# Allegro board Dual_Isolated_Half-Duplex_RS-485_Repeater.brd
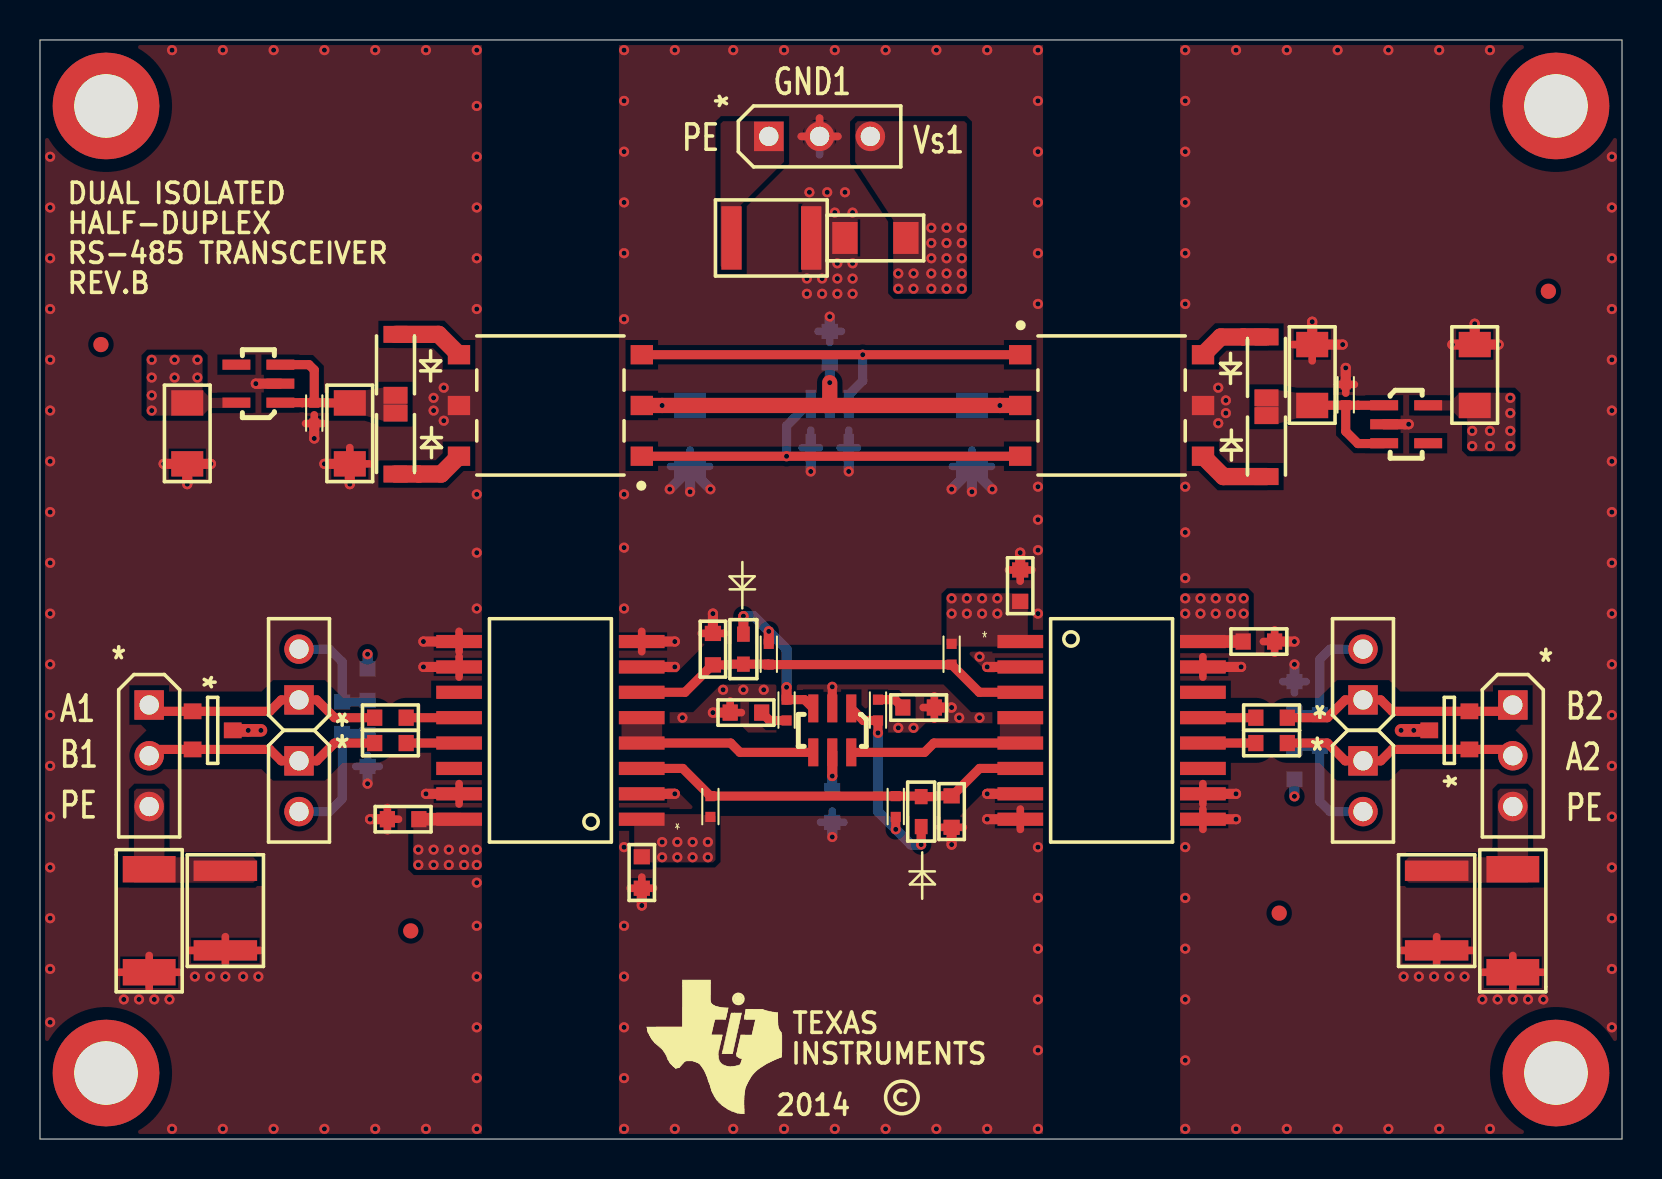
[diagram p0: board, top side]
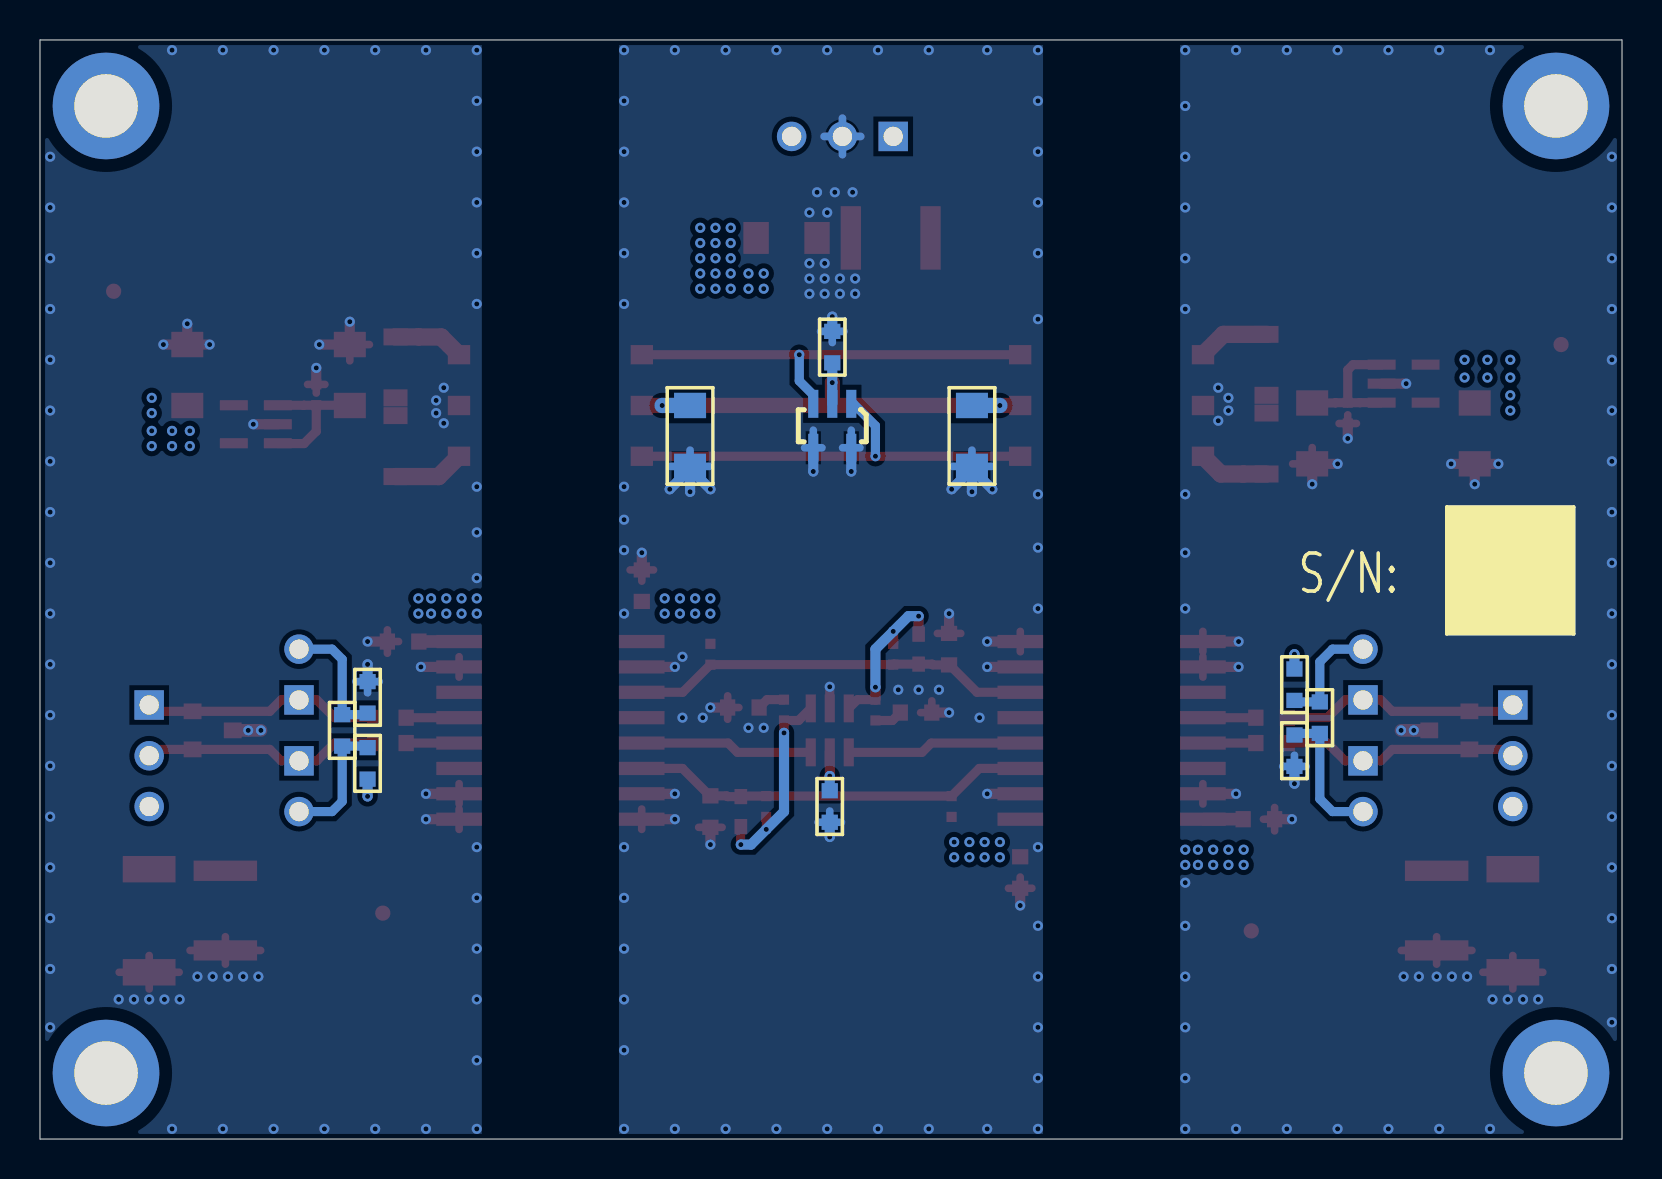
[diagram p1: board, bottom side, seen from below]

Outline 79.12 x 54.99 mm; copper layers: TOP, L2 GND, L3 PWR, BOTTOM. Coordinates in mm from the lower left corner of the outline.
Outline path: 0,54.99 79.12,54.99 79.12,0 0,0 0,54.99

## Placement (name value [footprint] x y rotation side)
C1  4.7uF  [1206]  41.78 45.09 180 top
C2  4700pF  [1812]  36.58 45.09 180 top
C3  0.1uF  [0603]  39.5 39.62 90 bottom
C4  4.7uF  [1206]  32.51 35.18 90 bottom
C5  4.7uF  [1206]  46.61 35.18 90 bottom
C6  4.7uF  [1206]  15.49 35.31 270 top
C7  10.0nF  [0402]  13.72 36.32 270 top
C8  4.7uF  [1206]  7.37 35.31 270 top
C9  4.7uF  [1206]  63.63 38.23 90 top
C10  10.0nF  [0402]  65.3 37.24 90 top
C11  4.7uF  [1206]  71.75 38.23 90 top
C12  4700pF  [1812]  9.27 11.43 90 top
C13  0.1uF  [0603]  18.16 16 0 top
C14  0.1uF  [0603]  30.1 13.34 90 top
C15  0.1uF  [0603]  39.62 16.64 270 bottom
C16  100pF  [0603]  35.31 21.34 0 top
C17  100pF  [0603]  43.94 21.59 0 top
C18  0.1uF  [0603]  49.02 27.69 270 top
C19  0.1uF  [0603]  60.96 24.89 0 top
C20  4700pF  [1812]  69.85 11.43 270 top
C21  100pF  [0603]  33.66 24.51 270 top
C22  100pF  [0603]  45.59 16.38 90 top
D1  RB168M-40  [DIODE_SOD_123F]  17.78 38.73 90 top
D2  RB168M-40  [DIODE_SOD_123F]  17.78 34.8 270 top
D3  RB168M-40  [DIODE_SOD_123F]  61.34 38.61 90 top
D4  RB168M-40  [DIODE_SOD_123F]  61.34 34.67 270 top
D5  SM712  [SOT_23_321]  8.64 20.45 270 top
D6  1N4448WT  [SOD_523]  35.18 24.51 270 top
D7  1N4448WT  [SOD_523]  44.07 16.38 90 top
D8  SM712  [SOT_23_321]  70.48 20.45 90 top
J1  HMTSW-103-07-G-S-.240  [HDR_THVT_1X3_100]  36.45 50.16 90 top
J2  1725669  [HDR_THVT_1X3_100]  5.46 21.72 0 top
J3  1725669  [HDR_THVT_1X3_100]  73.66 21.72 0 top
JP1  HEADER_1x2_100_430L  [HDR_THVT_1X2_100]  12.95 18.92 0 top
JP2  HEADER_1x2_100_430L  [HDR_THVT_1X2_100]  12.95 21.97 180 top
JP3  HEADER_1x2_100_430L  [HDR_THVT_1X2_100]  66.17 18.92 0 top
JP4  HEADER_1x2_100_430L  [HDR_THVT_1X2_100]  66.17 21.97 180 top
M*  -  [unnamed]  75.82 3.3 0 top
M*#2  -  [unnamed]  3.3 51.69 0 top
M*#3  -  [unnamed]  75.82 51.69 0 top
M*#4  -  [unnamed]  3.3 3.3 0 top
NOREF  -  [unnamed]  75.44 42.42 0 top
NOREF#2  -  [#2]  0 54.99 0 top
NOREF#3  -  [unnamed]  3.05 39.75 0 top
NOREF#4  -  [#2]  0 0 90 top
NOREF#5  -  [#2]  30.35 1.27 0 top
NOREF#6  -  [#2]  80.77 0.64 0 top
NOREF#7  -  [unnamed]  18.54 10.41 0 top
NOREF#8  -  [unnamed]  61.98 11.3 0 top
NOREF#9  -  [#2]  48.01 6.86 180 bottom
NOREF#10  -  [#2]  14.73 6.22 180 bottom
NOREF#11  -  [#2]  15.75 28.45 180 bottom
R1  590  [0603]  16.38 22.73 270 bottom
R2  133  [0603]  15.11 21.08 270 bottom
R3  590  [0603]  16.38 19.43 270 bottom
R4  10  [0603]  17.53 21.08 0 top
R5  10  [0603]  17.53 19.81 0 top
R6  1M  [2010]  5.46 10.92 90 top
R7  10K  [0402]  33.53 16.64 90 top
R8  51  [0402]  36.45 24.26 90 top
R9  51  [0402]  42.8 16.64 90 top
R10  10K  [0402]  45.59 24.26 270 top
R11  10  [0603]  61.59 19.81 0 top
R12  10  [0603]  61.59 21.08 0 top
R13  1M  [2010]  73.66 10.92 270 top
R14  590  [0603]  62.74 18.8 90 bottom
R15  133  [0603]  64.01 20.45 90 bottom
R16  590  [0603]  62.74 22.1 90 bottom
R17  300  [0402]  37.34 21.46 270 top
R18  300  [0402]  41.91 21.46 90 top
T1  WE 760390014  [TFMR_6_281X265]  25.53 36.7 180 top
T2  WE 760390014  [TFMR_6_281X265]  53.59 36.7 0 top
U1  SN6501DBV  [SOT23_5]  39.5 35.69 270 bottom
U2  TPS76350DBV  [SOT23_5]  10.92 37.8 180 top
U3  TPS76350DBV  [SOT23_5]  68.33 35.76 0 top
U4  ISO3082DW  [SOIC_16_410X299_50]  25.53 20.45 180 top
U5  ISO3082DW  [SOIC_16_410X299_50]  53.59 20.45 0 top
U6  SN74LVC2G14DBV  [SOT23_6]  39.62 20.45 270 top

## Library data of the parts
C1 C2 C4 C5 C12 C20 = CAP_1206_2.2uF
C3 C13-C15 C18 C19 = CAP_0603_0.1uF_H
C6 C8 C9 C11 = CAP_1206_10uF
C7 C10 = CAP_0402_0.001uF
C16 C17 C21 C22 = CAP_0603_100pF
D1-D4 = DIODE_MA2S78400L_1
D5 D8 = DIODE_TVS
D6 D7 = DIODE_10BQ060
J1 = HEADER_1x3_100
J2 J3 = HEADER_1x3_7
JP1-JP4 = JUMPER_1x2_100
R1-R3 R14-R16 = Res_0603_330
R4 R5 R11 R12 = Res_0603_10
R6 R13 = RES_1206_H
R7 R10 = Res_0402_10k
R8 R9 R17 R18 = Res_0402_49.9
T1 T2 = TFMR_6_WE-PP_760390014
U1 = SN6501DBV
U2 U3 = TPS76350DBV
U4 U5 = ISO3082DW
U6 = SN74LVC2G14DBV

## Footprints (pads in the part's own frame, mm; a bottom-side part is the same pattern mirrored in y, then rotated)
0402
  rect 0.508x0.508 smd: 1(-0.521,0) 2(0.521,0)
0603
  rect 0.762x0.813 smd: 1(-0.787,0) 2(0.787,0)
1206
  rect 1.27x1.6 smd: 1(-1.524,0) 2(1.524,0)
1812
  rect 1.016x3.175 smd: 1(-1.994,0) 2(1.994,0)
2010
  rect 1.321x2.642 smd: 1(-2.578,0) 2(2.578,0)
DIODE_SOD_123F
  rect 0.85x1.2 smd: 1(-1.525,0) 2(1.525,0)
HDR_THVT_1X2_100
  rect 1.473x1.473 hole 0.965: 1(0,0)
  round 1.473 hole 0.965: 2(0,-2.54)
HDR_THVT_1X3_100
  rect 1.473x1.473 hole 0.965: 1(0,0)
  round 1.473 hole 0.965: 2(0,-2.54) 3(0,-5.08)
SOD_523
  rect 0.762x0.635 smd: 1(0.75,0) 2(-0.75,0)
SOIC_16_410X299_50
  rect 2.286x0.66 smd: 1(-4.566,4.445) 2(-4.566,3.175) 3(-4.566,1.905) 4(-4.566,0.635) 5(-4.566,-0.635) 6(-4.566,-1.905) 7(-4.566,-3.175) 8(-4.566,-4.445) 9(4.566,-4.445) 10(4.566,-3.175) 11(4.566,-1.905) 12(4.566,-0.635) 13(4.566,0.635) 14(4.566,1.905) 15(4.566,3.175) 16(4.566,4.445)
SOT23_5
  rect 1.397x0.508 smd: 1(-1.1,0.95) 2(-1.1,0) 3(-1.1,-0.95) 4(1.1,-0.95) 5(1.1,0.95)
SOT23_6
  rect 1.397x0.508 smd: 1(-1.1,0.95) 2(-1.1,0) 3(-1.1,-0.95) 4(1.1,-0.95) 5(1.1,0) 6(1.1,0.95)
SOT_23_321
  rect 0.787x0.889 smd: 1(-0.953,-1.003) 2(0.953,-1.003) 3(0,1.003)
TFMR_6_281X265
  rect 1.118x0.965 smd: 1(-4.572,2.54) 2(-4.572,0) 3(-4.572,-2.54) 4(4.572,-2.54) 5(4.572,0) 6(4.572,2.54)
unnamed
  round 0.762 smd: (0,0)

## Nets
GND: C9.2 C10.2 C11.2 C19.2 C20.2 D8.3 R13.2 R16.2 T2.5(SECONDARY_CT) U3.2(GND) U5.9(GND2#9) U5.10(GND2#10) U5.15(GND2#15)
GND_SIGNAL: C6.2 C7.2 C8.2 C12.1 C13.1 D5.3 R3.2 R6.1 T1.5(SECONDARY_CT) U2.2(GND) U4.9(GND2#9) U4.10(GND2#10) U4.15(GND2#15)
0: C1.2 C2.1 C3.2 C4.1 C5.1 C14.1 C15.2 C16.1 C17.2 C18.1 C21.1 C22.1 J1.2 U1.4(GND#4) U1.5(GND#5) U4.2(GND1#2) U4.7(GND1#7) U4.8(GND1#8) U5.2(GND1#2) U5.7(GND1#7) U5.8(GND1#8) U6.2(GND)
VS1: C1.1 C3.1 C4.2 C5.2 C14.2 C15.1 C18.2 J1.3 R7.1 R10.1 T1.2(PRIMARY_CT) T2.2(PRIMARY_CT) U1.2(VCC) U4.1(VCC1) U5.1(VCC1) U6.5(VCC)
VS2: C8.1 C13.2 R1.1 U2.5(OUT) U4.16(VCC2)
VS3: C11.1 C19.1 R14.1 U3.5(OUT) U5.16(VCC2)
N6187763: C6.1 C7.1 D1.1(A) D2.1(A) U2.1(IN) U2.3(EN)
N6187778: C9.1 C10.1 D3.1(A) D4.1(A) U3.1(IN) U3.3(EN)
N6187816: T1.3(PRIMARY) T2.1(PRIMARY_DOT) U1.3(D2)
N6187836: T1.1(PRIMARY_DOT) T2.3(PRIMARY) U1.1(D1)
N6188463: D4.2(C) T2.4(SECONDARY)
N6189820: JP2.2 R1.2 R2.1
N6189824: JP1.2 R2.2 R3.1
N6189852: JP3.2 R14.2 R15.1
N6189856: JP4.2 R15.2 R16.1
N6190014: D5.1 J2.1 JP2.1 R4.1
N6190029: D5.2 J2.2 JP1.1 R5.1
N6190181: D8.2 J3.1 JP4.1 R12.2
N6190196: D8.1 J3.2 JP3.1 R11.2
N6190760: C2.2 J1.1
N6191068: C12.2 J2.3 R6.2
N6191267: C20.1 J3.3 R13.1
N6191867: D6.2(ANODE) R8.2 R17.1 U6.3(2A)
N6191878: D7.2(ANODE) R9.1 R18.1 U6.1(1A)
N6193179: R5.2 U4.13(B)
N6193213: R4.2 U4.12(A)
N6193644: C21.2 D6.1(CATHODE) R8.1 R10.2 U4.6(D) U5.3(R)
N6193872: R12.1 U5.13(B)
N6193884: R11.1 U5.12(A)
N6194289: C22.2 D7.1(CATHODE) R7.2 R9.2 U4.3(R) U5.6(D)
N6195266: U4.4(R\E\) U4.5(DE) U6.4(2Y)
N6195278: U5.4(R\E\) U5.5(DE) U6.6(1Y)
N6200692: C16.2 R17.2
N6207751: D3.2(C) T2.6(SECONDARY_DOT)
N6215252: D1.2(C) T1.4(SECONDARY)
N6215283: D2.2(C) T1.6(SECONDARY_DOT)
N61917820: C17.1 R18.2

Pads without a net: U2 4; U3 4; U4 11 14; U5 11 14

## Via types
v1: diameter 0.508, hole 0.254, TOP to BOTTOM, 322 vias

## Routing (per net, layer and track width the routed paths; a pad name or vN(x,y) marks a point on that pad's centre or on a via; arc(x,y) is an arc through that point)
GND: length 35.7
  TOP w0.381: C19.2 61.75,25.48 ; C19.2 61.75,24.31 ; C19.2 61.19,24.89 ; C10.2 65.74,37.76 ; C10.2 64.87,37.76 ; C10.2 65.3,37.32 ; 63.63,38.94 C9.2 62.65,39.75 ; C20.2 69.85,10.12 ; C20.2 69.85,8.75 ; C20.2 68.08,9.44 ; C20.2 71.62,9.44 ; 72.16,8.34 R13.2 ; R13.2 75.16,8.34 ; R13.2 73.66,9.18 ; R13.2 73.66,7.51 ; 58.16,16.76 U5.10 58.16,17.78 ; 58.16,23.11 U5.15 58.16,24.13 ; 58.16,15.49 U5.9 58.16,16.51
  TOP w0.508: C11.2 v1(71.75,40.79) ; C11.2 v1(70.64,39.75) ; C11.2 v1(72.95,39.75) ; U5.10 v1(59.82,17.27) ; v1(68.45,35.76) U3.2 ; v1(63.63,40.89) C9.2 v1(65.15,39.75) ; C10.2 v1(65.3,38.58) ; U5.15 v1(60.07,23.62) ; U5.9 v1(59.82,16) ; C19.2 v1(62.74,24.89)
  TOP w0.635: D8.3 v1(68.71,20.45) v1(68.07,20.45)
  BOTTOM w0.381: 62.15,22.89 R16.2 ; R16.2 62.74,22.33 ; R16.2 63.32,22.89
  BOTTOM w0.508: R16.2 v1(62.74,23.75)
  vias: v1(57.28,54.48) v1(57.28,51.94) v1(57.28,49.4) v1(57.28,46.86) v1(57.28,44.32) v1(57.28,41.78) v1(57.28,32.64) v1(57.28,30.35) v1(57.28,28.07) v1(57.28,14.61) v1(57.28,12.06) v1(57.28,9.53) v1(57.28,6.99) v1(57.28,3.94) v1(57.28,0.51) v1(58.93,37.59) v1(58.93,35.81) v1(59.31,36.96) v1(59.31,36.32) v1(59.82,54.48) v1(59.82,0.51) v1(62.36,54.48) v1(62.36,0.51) v1(64.9,54.48) v1(64.9,0.51) v1(67.44,54.48) v1(67.44,0.51) v1(68.2,8.13) v1(68.96,8.13) v1(69.72,8.13) v1(69.98,54.48) v1(69.98,0.51) v1(70.48,8.13) v1(71.25,8.13) v1(72.14,6.99) v1(72.52,54.48) v1(72.52,0.51) v1(72.9,6.99) v1(73.66,6.99) v1(74.42,6.99) v1(75.18,6.99) v1(78.61,49.15) v1(78.61,46.61) v1(78.61,44.07) v1(78.61,41.53) v1(78.61,38.99) v1(78.61,36.45) v1(78.61,33.91) v1(78.61,31.37) v1(78.61,28.83) v1(78.61,26.29) v1(78.61,23.75) v1(78.61,21.21) v1(78.61,18.67) v1(78.61,16.13) v1(78.61,13.59) v1(78.61,11.05) v1(78.61,8.51) v1(78.61,5.59)
GND_SIGNAL: length 35.2
  TOP w0.381: 15.49,34.6 C6.2 16.47,33.78 ; C12.1 11.04,9.44 ; C12.1 9.27,8.75 ; C12.1 7.51,9.44 ; C12.1 9.27,10.12 ; 20.96,24.13 U4.10 20.96,23.11 ; 5.46,7.51 R6.1 ; R6.1 5.46,9.18 ; R6.1 6.96,8.34 ; R6.1 3.96,8.34 ; 20.96,17.78 U4.15 20.96,16.76 ; 17.37,15.42 C13.1 ; C13.1 17.37,16.59 ; C13.1 17.93,16 ; C7.2 13.72,36.23 ; C7.2 14.15,35.8 ; C7.2 13.28,35.8 ; 20.96,24.38 U4.9 20.96,25.4
  TOP w0.508: v1(10.79,37.8) U2.2 ; C8.2 v1(6.18,33.78) ; C8.2 v1(7.37,32.77) ; C8.2 v1(8.55,33.78) ; C13.1 v1(16.51,16) ; v1(15.49,32.77) C6.2 v1(14.22,33.78) ; U4.15 v1(19.3,17.27) ; C7.2 v1(13.72,35.05) ; U4.10 v1(19.18,23.62) ; U4.9 v1(19.18,24.89)
  TOP w0.635: D5.3 v1(10.41,20.45) v1(11.05,20.45)
  BOTTOM w0.381: R3.2 16.97,18.64 ; R3.2 16.38,19.2 ; R3.2 15.8,18.64
  BOTTOM w0.508: R3.2 v1(16.38,17.78)
  vias: v1(0.51,49.15) v1(0.51,46.61) v1(0.51,44.07) v1(0.51,41.53) v1(0.51,38.99) v1(0.51,36.45) v1(0.51,33.91) v1(0.51,31.37) v1(0.51,28.83) v1(0.51,26.29) v1(0.51,23.75) v1(0.51,21.21) v1(0.51,18.67) v1(0.51,16.13) v1(0.51,13.59) v1(0.51,11.05) v1(0.51,8.51) v1(0.51,5.84) v1(4.19,6.99) v1(4.95,6.99) v1(5.71,6.99) v1(6.48,6.99) v1(6.6,54.48) v1(6.6,0.51) v1(7.75,8.13) v1(8.51,8.13) v1(9.14,54.48) v1(9.14,0.51) v1(9.27,8.13) v1(10.16,8.13) v1(10.92,8.13) v1(11.68,54.48) v1(11.68,0.51) v1(14.22,54.48) v1(14.22,0.51) v1(16.76,54.48) v1(16.76,0.51) v1(19.3,54.48) v1(19.3,0.51) v1(19.68,37.08) v1(19.68,36.45) v1(20.19,37.59) v1(20.19,35.94) v1(21.84,54.48) v1(21.84,51.69) v1(21.84,49.15) v1(21.84,46.61) v1(21.84,44.07) v1(21.84,41.53) v1(21.84,32.26) v1(21.84,29.34) v1(21.84,26.54) v1(21.84,12.83) v1(21.84,10.67) v1(21.84,8.13) v1(21.84,5.59) v1(21.84,3.05) v1(21.84,0.51)
0: length 61.7
  TOP w0.381: 48.44,28.47 C18.1 ; C18.1 49.02,27.91 ; C18.1 49.61,28.47 ; 44.17,21.59 C17.2 ; C17.2 44.73,21.01 ; C17.2 44.73,22.17 ; 49.03,16.51 U5.8 49.03,15.49 ; C14.1 30.1,13.11 ; C14.1 30.68,12.55 ; C14.1 29.51,12.55 ; 38.07,50.16 J1.2 ; J1.2 38.99,51.08 ; J1.2 39.9,50.16 ; 45.01,15.6 C22.1 46.18,15.6 ; 35.08,21.34 C16.1 34.52,21.92 ; 34.24,25.3 C21.1 33.07,25.3 ; 30.09,24.38 U4.8 30.09,25.4
  TOP w0.457: U6.2 v1(39.62,22.63)
  TOP w0.508: C14.1 v1(30.1,11.68) ; U5.7 v1(47.37,17.27) ; U4.2 v1(31.75,17.27) ; C22.1 v1(45.59,14.73) ; C16.1 v1(33.66,21.34) ; U4.8 v1(31.75,24.89) ; U4.7 v1(31.75,23.62) ; U5.2 v1(47.37,23.62) ; C18.1 v1(49.02,29.34) ; C17.2 v1(45.59,21.59) ; C21.1 v1(33.66,26.29) ; U5.8 v1(47.37,16)
  L2 GND w0.381: J1.2 38.99,51.08 ; J1.2 39.9,50.16 ; J1.2 38.99,49.25 ; J1.2 38.07,50.16
  BOTTOM w0.381: J1.2 39.9,50.16 ; J1.2 38.07,50.16 ; J1.2 38.99,51.08 ; J1.2 38.99,49.25 ; U1.5 38.55,35.46 ; U1.5 38.98,34.59 ; U1.5 38.11,34.59 ; C15.2 39.62,16.41 ; C15.2 40.21,15.85 ; C15.2 39.04,15.85 ; C5.1 46.61,34.47 ; C5.1 47.59,33.66 ; C5.1 45.63,33.66 ; 39.5,39.85 C3.2 ; C3.2 40.08,40.41 ; C3.2 38.91,40.41 ; U1.4 40.88,34.59 ; U1.4 40.01,34.59 ; U1.4 40.45,35.46 ; 31.53,33.66 C4.1 ; C4.1 33.49,33.66 ; C4.1 32.51,34.47
  BOTTOM w0.508: 46.61,33.53 v1(46.61,32.38) ; 46.61,33.53 C5.1 ; 46.61,33.53 v1(47.62,32.51) ; 46.61,33.53 v1(45.59,32.51) ; C15.2 v1(39.62,15.11) ; 32.51,33.53 C4.1 ; 32.51,33.53 v1(32.51,32.38) ; 32.51,33.53 v1(31.5,32.51) ; 32.51,33.53 v1(33.53,32.51) ; C3.2 v1(39.5,41.15) ; U1.5 v1(38.55,33.4) ; U1.4 v1(40.45,33.4)
  vias: v1(29.21,54.48) v1(29.21,51.94) v1(29.21,49.4) v1(29.21,46.86) v1(29.21,44.32) v1(29.21,41.02) v1(29.21,32.26) v1(29.21,29.59) v1(29.21,26.54) v1(29.21,14.61) v1(29.21,10.67) v1(29.21,8.13) v1(29.21,5.59) v1(29.21,3.05) v1(29.21,0.51) v1(31.75,54.48) v1(31.75,0.51) v1(32.13,21.08) v1(34.16,22.48) v1(34.67,54.48) v1(34.67,0.51) v1(35.18,22.48) v1(36.2,22.48) v1(37.21,54.48) v1(37.21,0.51) v1(38.35,43.05) v1(38.35,42.29) v1(38.48,47.37) v1(39.12,43.05) v1(39.12,42.29) v1(39.37,47.37) v1(39.75,54.48) v1(39.75,46.35) v1(39.75,0.51) v1(39.88,43.81) v1(39.88,43.05) v1(39.88,42.29) v1(40.26,47.37) v1(40.64,46.35) v1(40.64,43.81) v1(40.64,43.05) v1(40.64,42.29) v1(42.29,54.48) v1(42.29,0.51) v1(42.93,20.57) v1(43.69,20.57) v1(44.83,54.48) v1(44.83,0.51) v1(45.97,21.08) v1(46.99,24.13) v1(46.99,21.08) v1(47.37,54.48) v1(47.37,0.51) v1(49.91,54.48) v1(49.91,51.94) v1(49.91,49.4) v1(49.91,46.86) v1(49.91,44.32) v1(49.91,41.78) v1(49.91,32.64) v1(49.91,30.99) v1(49.91,29.46) v1(49.91,26.29) v1(49.91,14.61) v1(49.91,12.06) v1(49.91,9.53) v1(49.91,6.99) v1(49.91,4.45) v1(49.91,0.51)
VS1: length 30.5
  TOP w0.508: U6.5 v1(39.62,18.16)
  TOP w0.762: 39.5,36.7 v1(31.11,36.7) T1.2 ; 39.5,36.7 v1(39.5,37.85) ; 39.5,36.7 v1(48.01,36.7) T2.2
  L3 PWR w0.381: J1.3 42.44,50.16 ; J1.3 40.61,50.16 ; J1.3 41.53,51.08 ; J1.3 41.53,49.25
  BOTTOM w0.508: C3.1 v1(39.5,37.85) U1.2 ; v1(39.62,18.16) C15.1
  BOTTOM w0.762: C4.2 v1(31.11,36.7) ; C5.2 v1(48.01,36.7)
  vias: v1(31.11,14.86) v1(31.11,14.1) v1(31.88,14.86) v1(31.88,14.1) v1(32.64,14.86) v1(32.64,14.1) v1(33.4,14.86) v1(33.4,14.1) v1(42.93,43.31) v1(42.93,42.55) v1(43.69,43.31) v1(43.69,42.55) v1(44.58,45.59) v1(44.58,44.83) v1(44.58,44.07) v1(44.58,43.31) v1(44.58,42.55) v1(45.34,45.59) v1(45.34,44.83) v1(45.34,44.07) v1(45.34,43.31) v1(45.34,42.55) v1(45.59,27.05) v1(45.59,26.29) v1(46.1,45.59) v1(46.1,44.83) v1(46.1,44.07) v1(46.1,43.31) v1(46.1,42.55) v1(46.35,27.05) v1(46.35,26.29) v1(47.12,27.05) v1(47.12,26.29) v1(47.88,27.05) v1(47.88,26.29)
VS2: length 2.7
  TOP w0.635: U4.16 C13.2
  BOTTOM w0.508: R1.1 v1(16.38,24.26)
  vias: v1(5.59,38.99) v1(5.59,38.1) v1(5.59,37.21) v1(5.59,36.45) v1(6.73,38.99) v1(6.73,38.1) v1(7.87,38.99) v1(7.87,38.1) v1(18.92,14.48) v1(18.92,13.72) v1(19.68,14.48) v1(19.68,13.72) v1(20.45,14.48) v1(20.45,13.72) v1(21.21,14.48) v1(21.21,13.72) v1(21.84,14.48) v1(21.84,13.72)
VS3: length 2.9
  TOP w0.635: U5.16 C19.1
  BOTTOM w0.508: R14.1 v1(62.74,17.14)
  vias: v1(57.28,27.05) v1(57.28,26.29) v1(58.04,27.05) v1(58.04,26.29) v1(58.8,27.05) v1(58.8,26.29) v1(59.56,27.05) v1(59.56,26.29) v1(60.2,27.05) v1(60.2,26.29) v1(71.63,35.43) v1(71.63,34.67) v1(72.52,35.43) v1(72.52,34.67) v1(73.53,37.08) v1(73.53,36.32) v1(73.53,35.43) v1(73.53,34.67)
N6187763: length 6.9
  TOP w0.457: C7.1 13.72,38.48 13.45,38.75 U2.3 ; C7.1 14.33,36.84 14.34,36.83 C6.1 ; C7.1 13.11,36.84 13.1,36.85 U2.1
N6187778: length 7.1
  TOP w0.457: C10.1 65.3,35.41 65.91,34.8 67.21,34.8 U3.3 ; C10.1 63.64,36.72 63.63,36.7 ; C10.1 65.91,36.72 65.92,36.71 U3.1
N6187816: length 21.7
  TOP w0.457: T1.3 v1(41.15,39.24) T2.1
  BOTTOM w0.457: v1(41.15,39.24) 41.15,37.93 40.45,37.23 U1.3
N6187836: length 22.1
  TOP w0.457: T2.3 v1(37.34,34.16) T1.1
  BOTTOM w0.457: v1(37.34,34.16) 37.34,35.69 38.44,36.79 U1.1
N6188463: length 3.6
  TOP w0.864: D4.2 59.18,33.15 T2.4
N6189820: length 5.7
  BOTTOM w0.457: R1.2 16.31,21.87 R2.1 15.11,23.88 14.48,24.51 JP2.2
N6189824: length 7
  BOTTOM w0.457: JP1.2 14.48,16.38 15.11,17.02 R2.2 16.31,20.29 R3.1
N6189852: length 6.4
  BOTTOM w0.457: R14.2 62.81,19.66 R15.1 64.01,16.89 64.52,16.38 JP3.2
N6189856: length 6.4
  BOTTOM w0.457: R16.1 62.81,21.23 R15.2 64.01,24 64.52,24.51 JP4.2
N6190014: length 12
  TOP w0.457: R4.1 14.73,21.08 13.84,21.97 JP2.1 12.06,21.97 11.49,21.4 D5.1 5.78,21.4 J2.1
N6190029: length 12
  TOP w0.457: R5.1 14.73,19.81 13.84,18.92 JP1.1 12.06,18.92 11.49,19.49 D5.2 5.78,19.49 J2.2
N6190181: length 12
  TOP w0.457: J3.1 73.34,21.4 D8.2 67.63,21.4 67.06,21.97 JP4.1 65.28,21.97 64.39,21.08 R12.2
N6190196: length 12
  TOP w0.457: R11.2 64.39,19.81 65.28,18.92 JP3.1 67.06,18.92 67.63,19.49 D8.1 73.34,19.49 J3.2
N6191867: length 8.4
  TOP w0.457: U6.3 38.24,21.98 R17.1
  TOP w0.508: R8.2 v1(36.45,25.4) ; D6.2 v1(35.18,26.16) ; R17.1 v1(37.34,22.61)
  BOTTOM w0.508: v1(37.34,22.61) 37.34,24.51 v1(36.45,25.4) 35.69,26.16 v1(35.18,26.16)
N6191878: length 10.5
  TOP w0.457: R9.1 v1(42.8,15.49) ; v1(41.91,20.32) R18.1 41.18,20.94 U6.1 ; D7.2 v1(44.07,14.73)
  BOTTOM w0.508: v1(44.07,14.73) 43.56,14.73 v1(42.8,15.49) 41.91,16.38 v1(41.91,20.32)
N6193179: length 2.6
  TOP w0.457: U4.13 R5.2
N6193213: length 2.6
  TOP w0.457: U4.12 R4.2
N6193644: length 20.1
  TOP w0.457: U4.6 32.26,22.35 33.63,23.72 C21.2 34.47,23.72 34.51,23.76 D6.1 36.42,23.76 R8.1 R10.2 46.98,22.35 U5.3
N6193872: length 2.6
  TOP w0.457: U5.13 R12.1
N6193884: length 2.6
  TOP w0.457: U5.12 R11.1
N6194289: length 20.1
  TOP w0.457: U4.3 32.14,18.54 R7.2 R9.2 44.04,17.16 D7.1 44.74,17.13 44.78,17.17 C22.2 45.62,17.17 46.99,18.54 U5.6
N6195266: length 8.8
  TOP w0.457: U6.4 35.01,19.35 34.54,19.81 U4.4
N6195278: length 8.6
  TOP w0.457: U6.6 44.24,19.35 44.7,19.81 U5.5
N6200692: length 1.4
  TOP w0.457: R17.2 36.49,20.94 C16.2
N6207751: length 3.5
  TOP w0.864: D3.2 60.18,40.13 60.18,40.13 59.05,40.13 T2.6
N6215252: length 3.6
  TOP w0.864: T1.4 19.94,40.26 D1.2
N6215283: length 3.5
  TOP w0.864: T1.6 20.07,33.27 18.94,33.27 18.94,33.27 D2.2
N61917820: length 1.4
  TOP w0.457: R18.2 42.76,21.98 C17.1

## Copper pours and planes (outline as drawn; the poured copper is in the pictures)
GND on TOP: 57.02,54.74 57.02,0.25 78.87,0.25 78.87,54.74 ; 4 cut-outs
GND on TOP: 57.66,36.32 57.66,37.08 58.55,37.08 58.67,37.21 58.67,37.72 58.8,37.85 59.44,37.85 59.56,37.72 59.56,35.69 59.44,35.56 58.8,35.56 58.67,35.69 58.67,36.32
GND on BOTTOM: 57.02,54.74 57.02,0.25 78.87,0.25 78.87,54.74 ; 2 cut-outs
GND on L2 GND: 57.02,0.25 57.02,54.74 78.87,54.74 78.87,0.25
GND_SIGNAL on TOP: 0.25,54.74 0.25,0.25 22.1,0.25 22.1,54.74 ; 3 cut-outs
GND_SIGNAL on TOP: 21.46,36.32 21.46,37.08 20.57,37.08 20.45,37.21 20.45,37.72 20.32,37.85 19.56,37.85 19.43,37.72 19.43,35.81 19.56,35.69 20.32,35.69 20.45,35.81 20.45,36.32
GND_SIGNAL on BOTTOM: 0.25,54.74 0.25,0.25 22.1,0.25 22.1,54.74 ; 2 cut-outs
GND_SIGNAL on L2 GND: 0.25,54.74 0.25,0.25 22.1,0.25 22.1,54.74
0 on TOP: 28.96,54.74 28.96,0.25 50.16,0.25 50.16,54.74 ; 3 cut-outs
0 on TOP: 38.35,50.93 38.23,50.8 38.23,46.86 38.1,46.74 38.1,42.16 38.23,42.04 40.77,42.04 40.89,42.16 40.89,46.86 39.75,48.64 39.75,50.8 39.62,50.93
0 on BOTTOM: 28.96,54.74 28.96,0.25 50.16,0.25 50.16,54.74
0 on L2 GND: 28.96,0.25 28.96,54.74 50.16,54.74 50.16,0.25
VS1 on TOP: 29.72,13.84 29.72,16.26 33.78,16.26 33.78,13.97 33.66,13.84
VS1 on TOP: 49.4,27.3 49.4,24.64 45.34,24.64 45.34,27.18 45.47,27.3
VS1 on TOP: 40.89,50.93 40.77,50.8 40.77,48.9 42.67,45.97 42.67,42.42 42.8,42.29 46.23,42.29 46.35,42.42 46.35,50.8 46.23,50.93
VS1 on L3 PWR: 28.96,54.74 28.96,0.25 50.16,0.25 50.16,54.74
VS2 on TOP: 10.41,36.58 8.51,36.58 8.13,36.2 5.46,36.2 5.33,36.32 5.33,39.12 5.46,39.24 8,39.24 8.13,39.12 8.13,37.47 8.51,37.08 10.41,37.08
VS2 on TOP: 18.67,16.26 18.67,13.59 18.8,13.46 21.97,13.46 22.1,13.59 22.1,16.26
VS2 on L3 PWR: 0.25,54.74 0.25,0.25 22.1,0.25 22.1,54.74
VS3 on TOP: 57.02,24.64 57.02,27.18 57.15,27.3 60.33,27.3 60.45,27.18 60.45,24.64
VS3 on TOP: 68.96,36.96 70.61,36.96 70.99,37.34 73.66,37.34 73.79,37.21 73.79,34.54 73.66,34.42 71.5,34.42 71.37,34.54 71.37,36.07 70.99,36.07 70.61,36.45 68.96,36.45
VS3 on L3 PWR: 57.02,54.74 57.02,0.25 78.87,0.25 78.87,54.74
N6187763 on TOP: 15.11,37.47 16.26,37.47 17.14,37.59 18.29,37.59 18.29,35.94 17.14,35.94 16.26,36.2 15.11,36.2
N6187778 on TOP: 60.83,37.47 61.98,37.47 62.87,37.34 64.01,37.34 64.01,36.07 62.87,36.07 61.98,35.81 60.83,35.81
N6190760 on TOP: 37.21,50.93 37.21,48.9 35.05,46.74 35.05,43.56 34.16,43.56 34.04,43.69 34.04,50.8 34.16,50.93
N6191068 on TOP: 4.83,17.53 4.7,17.4 4.7,12.83 10.67,12.83 10.79,12.95 10.79,13.97 10.67,14.1 6.22,14.1 6.22,17.4 6.1,17.53
N6191267 on TOP: 74.3,17.53 74.42,17.4 74.42,12.83 68.45,12.83 68.33,12.95 68.33,13.97 68.45,14.1 72.9,14.1 72.9,17.4 73.03,17.53
N6195266 on TOP: 29.08,21.34 29.08,19.56 31.11,19.56 31.11,21.34
N6195278 on TOP: 48.01,21.34 48.01,19.56 50.04,19.56 50.04,21.34

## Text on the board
BOTTOM: LAYER 4 - BOT | 4
Board Geometry/Soldermask Bottom: LAYER 6 - SOLDERMASK BOTTOM | 6
Package Geometry/Pastemask Bottom: lAYER 8 - PASTEMASK BOT | 8
Ref Des/Silkscreen Bottom: LAYER 10 - SILKSCREEN BOT | 10
TOP: LAYER 1 - TOP | 1
Board Geometry/Soldermask Top: LAYER 5 - SOLDERMASK TOP | 5
Package Geometry/Pastemask Top: LAYER 7 - PASTEMASK TOP | 7
Ref Des/Silkscreen Top: DUAL ISOLATED | HALF-DUPLEX | RS-485 TRANSCEIVER | REV.B | INSTRUMENTS | A1 | B1 | PE | GND1 | Vs1 | B2 | A2 | LAYER 9 - SILKSCREEN TOP | 9
L2 GND: LAYER 2 - GND | 2
L3 PWR: LAYER 3 - PWR | 3
XSECTION_CHART: *  SURFACE - AIR 0 MIL | *  DIELECTRIC - SOLDERMASK_LPI_P8MI 0.8 MIL | *  DIELECTRIC - FILL_2113X3_PCL-370 10.86 MIL | *  DIELECTRIC - CORE_FIL_PCL-370HR 32.4 MIL | 1-4
PAGE_OUTLINE: GENERAL NOTES. UNLESS OTHERWISE SPECIFIED | 1.  ALL FABRICATION ITEMS MUST MEET OR EXCEED BEST | INDUSTRY PRACTICE : IPC-A-600C (Commercial std.) | 2.  LAMINATE MATERIAL  :  FR4 POLYCLAD 370 or EQUIVALENT | 3.  COPPER WEIGHT  : 1oz START INTERNAL, 1/2oz START EXTERNAL | 4.  FINISHED BOARD THICKNESS :  .062  +/- 10% | 5.  MAXIMUM WARP AND TWIST TO BE :  .005 INCH PER INCH | 6.  MINIMUM COPPER WALL THICKNESS OF PLATED-THRU | HOLES TO BE .001 INCH. THERE MUST BE 1MIL OR GREATER PLATING ON | EACH SIDE OF THE BARREL WHEN VIEWED IN THE CROSS SECTION | 7.  MINIMUM ANNULAR RING OF PLATED-THRU HOLES | TO BE .002 INCH | 8.  MAXIMUM ALLOWABLE LINE REDUCTION TO BE | 20% OR .002 WHICHEVER IS SMALLER | 10. 0.018 SIGNAL LINES ON LAYER 1 TO BE | IMPEDANCE CONTROLLED 50 OHMS +/- 10% | 11. TRACE WIDTH CALCULATIONS ARE STARTING VALUES. BOARD SHOP MAY ADJUST | TRACE WIDTHS TO COMPENSATE FOR PROCESS. | 12. DIELECTRIC CONSTANTS ARE         CORE : 3.9 | PREPREG : 3.9 | 15. THIEVING IS NOT ALLOWED | PROCESS NOTES | 1. CIRCUITRY ON OUTER LAYERS TO BE PLATED WITH : ENIG | 3. SOLDERMASK BOTH SIDES PER ARTWORK  :  GREEN LPI | 4. SILKSCREEN BOTH SIDES PER ARTWORK  :  COLOR = WHITE | LAYER 11 - FAB | 11
DISPLAY_TOP: Half-Duplex RS-485 Repeater
User.5: FIGURE | SIZE | 10.0 | 38.0 | 125.0 | DRILL CHART: TOP to BOTTOM | ALL UNITS ARE IN MILS | TOLERANCE | +3.0/-3.0 | +2.0/-2.0 | PLATED | QTY | 322 | 17 | 4
